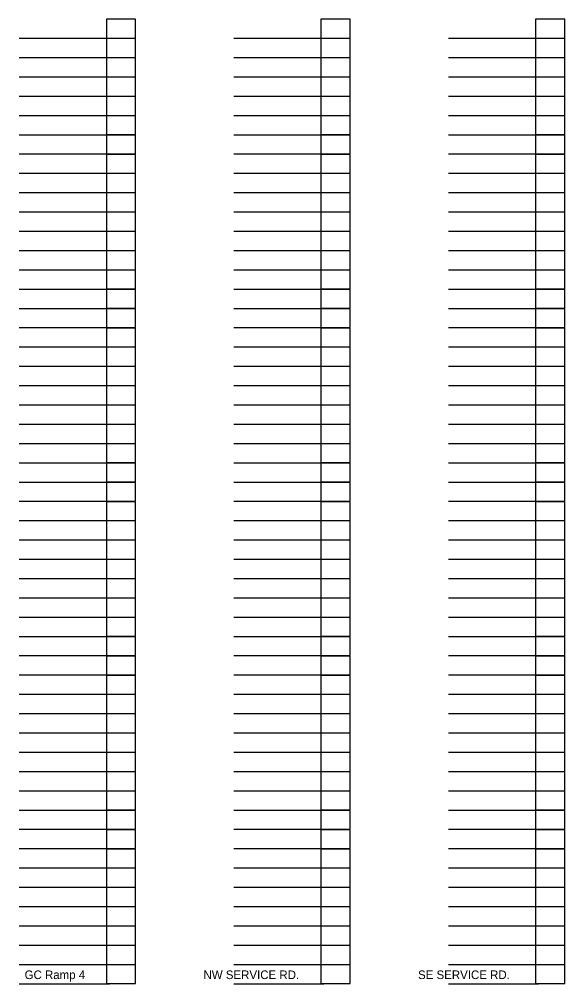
# Model space of a CAD drawing. Extents: x 625451 to 4181825, y 337941 to 441164.
# Drawn here: x 704151 to 716862, y 373673 to 396164 of the extents above; entities that cross this region are included whole.
import ezdxf

# ---------------------------------------------------------------- set-up
doc = ezdxf.new("R2010")
doc.units = 0
for name, color, linetype in [('PLOT_BDR-NOTUSED', 7, 'Continuous'), ('R_CX_Layout-GCRamp4', 7, 'Continuous'), ('R_CX_LAYOUT-NW SERVICE RD', 7, 'Continuous'), ('R_CX_LAYOUT-SE SERVICE RD', 7, 'Continuous'), ('R_No Plot_SEG2_FR', 7, 'Continuous')]:
    doc.layers.add(name, color=color, linetype=linetype)

msp = doc.modelspace()

# ---------------------------------------------------------------- linework, layer by layer
at = {"layer": 'PLOT_BDR-NOTUSED'}
for points in [[(706862, 396164), (706182, 396164), (706182, 395724), (706862, 395724)], [(711862, 396164), (711182, 396164), (711182, 395724), (711862, 395724)], [(716862, 396164), (716182, 396164), (716182, 395724), (716862, 395724)], [(706862, 395714), (706182, 395714), (706182, 395274), (706862, 395274)], [(711862, 395714), (711182, 395714), (711182, 395274), (711862, 395274)], [(716862, 395714), (716182, 395714), (716182, 395274), (716862, 395274)], [(706862, 395264), (706182, 395264), (706182, 394824), (706862, 394824)], [(711862, 395264), (711182, 395264), (711182, 394824), (711862, 394824)], [(716862, 395264), (716182, 395264), (716182, 394824), (716862, 394824)], [(706862, 394814), (706182, 394814), (706182, 394374), (706862, 394374)], [(711862, 394814), (711182, 394814), (711182, 394374), (711862, 394374)], [(716862, 394814), (716182, 394814), (716182, 394374), (716862, 394374)], [(706862, 394364), (706182, 394364), (706182, 393924), (706862, 393924)], [(711862, 394364), (711182, 394364), (711182, 393924), (711862, 393924)], [(716862, 394364), (716182, 394364), (716182, 393924), (716862, 393924)], [(706862, 393914), (706182, 393914), (706182, 393474), (706862, 393474)], [(711862, 393914), (711182, 393914), (711182, 393474), (711862, 393474)], [(716862, 393914), (716182, 393914), (716182, 393474), (716862, 393474)], [(706862, 393464), (706182, 393464), (706182, 393024), (706862, 393024)], [(711862, 393464), (711182, 393464), (711182, 393024), (711862, 393024)], [(716862, 393464), (716182, 393464), (716182, 393024), (716862, 393024)], [(706862, 393014), (706182, 393014), (706182, 392574), (706862, 392574)], [(711862, 393014), (711182, 393014), (711182, 392574), (711862, 392574)], [(716862, 393014), (716182, 393014), (716182, 392574), (716862, 392574)], [(706862, 392564), (706182, 392564), (706182, 392124), (706862, 392124)], [(711862, 392564), (711182, 392564), (711182, 392124), (711862, 392124)], [(716862, 392564), (716182, 392564), (716182, 392124), (716862, 392124)], [(706862, 392114), (706182, 392114), (706182, 391674), (706862, 391674)], [(711862, 392114), (711182, 392114), (711182, 391674), (711862, 391674)], [(716862, 392114), (716182, 392114), (716182, 391674), (716862, 391674)], [(706862, 391664), (706182, 391664), (706182, 391224), (706862, 391224)], [(711862, 391664), (711182, 391664), (711182, 391224), (711862, 391224)], [(716862, 391664), (716182, 391664), (716182, 391224), (716862, 391224)], [(706862, 391214), (706182, 391214), (706182, 390774), (706862, 390774)], [(711862, 391214), (711182, 391214), (711182, 390774), (711862, 390774)], [(716862, 391214), (716182, 391214), (716182, 390774), (716862, 390774)], [(706862, 390764), (706182, 390764), (706182, 390324), (706862, 390324)], [(711862, 390764), (711182, 390764), (711182, 390324), (711862, 390324)], [(716862, 390764), (716182, 390764), (716182, 390324), (716862, 390324)], [(706862, 390314), (706182, 390314), (706182, 389874), (706862, 389874)], [(711862, 390314), (711182, 390314), (711182, 389874), (711862, 389874)], [(716862, 390314), (716182, 390314), (716182, 389874), (716862, 389874)], [(706862, 389864), (706182, 389864), (706182, 389424), (706862, 389424)], [(711862, 389864), (711182, 389864), (711182, 389424), (711862, 389424)], [(716862, 389864), (716182, 389864), (716182, 389424), (716862, 389424)], [(706862, 389414), (706182, 389414), (706182, 388974), (706862, 388974)], [(711862, 389414), (711182, 389414), (711182, 388974), (711862, 388974)], [(716862, 389414), (716182, 389414), (716182, 388974), (716862, 388974)], [(706862, 388964), (706182, 388964), (706182, 388524), (706862, 388524)], [(711862, 388964), (711182, 388964), (711182, 388524), (711862, 388524)], [(716862, 388964), (716182, 388964), (716182, 388524), (716862, 388524)], [(706862, 388514), (706182, 388514), (706182, 388074), (706862, 388074)], [(711862, 388514), (711182, 388514), (711182, 388074), (711862, 388074)], [(716862, 388514), (716182, 388514), (716182, 388074), (716862, 388074)], [(706862, 388064), (706182, 388064), (706182, 387624), (706862, 387624)], [(711862, 388064), (711182, 388064), (711182, 387624), (711862, 387624)], [(716862, 388064), (716182, 388064), (716182, 387624), (716862, 387624)], [(706862, 387614), (706182, 387614), (706182, 387174), (706862, 387174)], [(711862, 387614), (711182, 387614), (711182, 387174), (711862, 387174)], [(716862, 387614), (716182, 387614), (716182, 387174), (716862, 387174)], [(706862, 387164), (706182, 387164), (706182, 386724), (706862, 386724)], [(711862, 387164), (711182, 387164), (711182, 386724), (711862, 386724)], [(716862, 387164), (716182, 387164), (716182, 386724), (716862, 386724)], [(706862, 386714), (706182, 386714), (706182, 386274), (706862, 386274)], [(711862, 386714), (711182, 386714), (711182, 386274), (711862, 386274)], [(716862, 386714), (716182, 386714), (716182, 386274), (716862, 386274)], [(706862, 386264), (706182, 386264), (706182, 385824), (706862, 385824)], [(711862, 386264), (711182, 386264), (711182, 385824), (711862, 385824)], [(716862, 386264), (716182, 386264), (716182, 385824), (716862, 385824)], [(706862, 385814), (706182, 385814), (706182, 385374), (706862, 385374)], [(711862, 385814), (711182, 385814), (711182, 385374), (711862, 385374)], [(716862, 385814), (716182, 385814), (716182, 385374), (716862, 385374)], [(706862, 385364), (706182, 385364), (706182, 384924), (706862, 384924)], [(711862, 385364), (711182, 385364), (711182, 384924), (711862, 384924)], [(716862, 385364), (716182, 385364), (716182, 384924), (716862, 384924)], [(706862, 384914), (706182, 384914), (706182, 384474), (706862, 384474)], [(711862, 384914), (711182, 384914), (711182, 384474), (711862, 384474)], [(716862, 384914), (716182, 384914), (716182, 384474), (716862, 384474)], [(706862, 384464), (706182, 384464), (706182, 384024), (706862, 384024)], [(711862, 384464), (711182, 384464), (711182, 384024), (711862, 384024)], [(716862, 384464), (716182, 384464), (716182, 384024), (716862, 384024)], [(706862, 384014), (706182, 384014), (706182, 383574), (706862, 383574)], [(711862, 384014), (711182, 384014), (711182, 383574), (711862, 383574)], [(716862, 384014), (716182, 384014), (716182, 383574), (716862, 383574)], [(706862, 383564), (706182, 383564), (706182, 383124), (706862, 383124)], [(711862, 383564), (711182, 383564), (711182, 383124), (711862, 383124)], [(716862, 383564), (716182, 383564), (716182, 383124), (716862, 383124)], [(706862, 383114), (706182, 383114), (706182, 382674), (706862, 382674)], [(711862, 383114), (711182, 383114), (711182, 382674), (711862, 382674)], [(716862, 383114), (716182, 383114), (716182, 382674), (716862, 382674)], [(706862, 382664), (706182, 382664), (706182, 382224), (706862, 382224)], [(711862, 382664), (711182, 382664), (711182, 382224), (711862, 382224)], [(716862, 382664), (716182, 382664), (716182, 382224), (716862, 382224)], [(706862, 382214), (706182, 382214), (706182, 381774), (706862, 381774)], [(711862, 382214), (711182, 382214), (711182, 381774), (711862, 381774)], [(716862, 382214), (716182, 382214), (716182, 381774), (716862, 381774)], [(706862, 381764), (706182, 381764), (706182, 381324), (706862, 381324)], [(711862, 381764), (711182, 381764), (711182, 381324), (711862, 381324)], [(716862, 381764), (716182, 381764), (716182, 381324), (716862, 381324)], [(706862, 381314), (706182, 381314), (706182, 380874), (706862, 380874)], [(711862, 381314), (711182, 381314), (711182, 380874), (711862, 380874)], [(716862, 381314), (716182, 381314), (716182, 380874), (716862, 380874)], [(706862, 380864), (706182, 380864), (706182, 380424), (706862, 380424)], [(711862, 380864), (711182, 380864), (711182, 380424), (711862, 380424)], [(716862, 380864), (716182, 380864), (716182, 380424), (716862, 380424)], [(706862, 380414), (706182, 380414), (706182, 379974), (706862, 379974)], [(711862, 380414), (711182, 380414), (711182, 379974), (711862, 379974)], [(716862, 380414), (716182, 380414), (716182, 379974), (716862, 379974)], [(706862, 379964), (706182, 379964), (706182, 379524), (706862, 379524)], [(711862, 379964), (711182, 379964), (711182, 379524), (711862, 379524)], [(716862, 379964), (716182, 379964), (716182, 379524), (716862, 379524)], [(706862, 379514), (706182, 379514), (706182, 379074), (706862, 379074)], [(711862, 379514), (711182, 379514), (711182, 379074), (711862, 379074)], [(716862, 379514), (716182, 379514), (716182, 379074), (716862, 379074)], [(706862, 379064), (706182, 379064), (706182, 378624), (706862, 378624)], [(711862, 379064), (711182, 379064), (711182, 378624), (711862, 378624)], [(716862, 379064), (716182, 379064), (716182, 378624), (716862, 378624)], [(706862, 378614), (706182, 378614), (706182, 378174), (706862, 378174)], [(711862, 378614), (711182, 378614), (711182, 378174), (711862, 378174)], [(716862, 378614), (716182, 378614), (716182, 378174), (716862, 378174)], [(711862, 378164), (711182, 378164), (711182, 377724), (711862, 377724)], [(716862, 378164), (716182, 378164), (716182, 377724), (716862, 377724)], [(711862, 377714), (711182, 377714), (711182, 377274), (711862, 377274)], [(716862, 377714), (716182, 377714), (716182, 377274), (716862, 377274)], [(711862, 377264), (711182, 377264), (711182, 376824), (711862, 376824)], [(716862, 377264), (716182, 377264), (716182, 376824), (716862, 376824)], [(711862, 376814), (711182, 376814), (711182, 376374), (711862, 376374)], [(716862, 376814), (716182, 376814), (716182, 376374), (716862, 376374)], [(711862, 376364), (711182, 376364), (711182, 375924), (711862, 375924)]]:
    msp.add_lwpolyline(points, close=True, dxfattribs=at)
at = {"layer": 'R_CX_Layout-GCRamp4'}
for p, q in [((704151, 395723), (706250, 395723)), ((704151, 395273), (706250, 395273)), ((704151, 394823), (706250, 394823)), ((704151, 394373), (706250, 394373)), ((704151, 393923), (706250, 393923)), ((704151, 393473), (706250, 393473)), ((704151, 393023), (706250, 393023)), ((704151, 392573), (706250, 392573)), ((704151, 392123), (706250, 392123)), ((704151, 391673), (706250, 391673)), ((704151, 391223), (706250, 391223)), ((704151, 390773), (706250, 390773)), ((704151, 390323), (706250, 390323)), ((704151, 389873), (706250, 389873)), ((704151, 389423), (706250, 389423)), ((704151, 388973), (706250, 388973)), ((704151, 388523), (706250, 388523)), ((704151, 388073), (706250, 388073)), ((704151, 387623), (706250, 387623)), ((704151, 387173), (706250, 387173)), ((704151, 386723), (706250, 386723)), ((704151, 386273), (706250, 386273)), ((704151, 385823), (706250, 385823)), ((704151, 385373), (706250, 385373)), ((704151, 384923), (706250, 384923)), ((704151, 384473), (706250, 384473)), ((704151, 384023), (706250, 384023)), ((704151, 383573), (706250, 383573)), ((704151, 383123), (706250, 383123)), ((704151, 382673), (706250, 382673)), ((704151, 382223), (706250, 382223)), ((704151, 381773), (706250, 381773)), ((704151, 381323), (706250, 381323)), ((704151, 380873), (706250, 380873)), ((704151, 380423), (706250, 380423)), ((704151, 379973), (706250, 379973)), ((704151, 379523), (706250, 379523)), ((704151, 379073), (706250, 379073)), ((704151, 378623), (706250, 378623)), ((704151, 378173), (706250, 378173)), ((704151, 377723), (706250, 377723)), ((704151, 377273), (706250, 377273)), ((704151, 376823), (706250, 376823)), ((704151, 376373), (706250, 376373)), ((704151, 375923), (706250, 375923)), ((704151, 375473), (706250, 375473)), ((704151, 375023), (706250, 375023)), ((704151, 374573), (706250, 374573)), ((704151, 374123), (706250, 374123)), ((704151, 373673), (706250, 373673))]:
    msp.add_line(p, q, dxfattribs=at)
at = {"layer": 'R_CX_LAYOUT-NW SERVICE RD'}
for p, q in [((709151, 395723), (711250, 395723)), ((709151, 395273), (711250, 395273)), ((709151, 394823), (711250, 394823)), ((709151, 394373), (711250, 394373)), ((709151, 393923), (711250, 393923)), ((709151, 393473), (711250, 393473)), ((709151, 393023), (711250, 393023)), ((709151, 392573), (711250, 392573)), ((709151, 392123), (711250, 392123)), ((709151, 391673), (711250, 391673)), ((709151, 391223), (711250, 391223)), ((709151, 390773), (711250, 390773)), ((709151, 390323), (711250, 390323)), ((709151, 389873), (711250, 389873)), ((709151, 389423), (711250, 389423)), ((709151, 388973), (711250, 388973)), ((709151, 388523), (711250, 388523)), ((709151, 388073), (711250, 388073)), ((709151, 387623), (711250, 387623)), ((709151, 387173), (711250, 387173)), ((709151, 386723), (711250, 386723)), ((709151, 386273), (711250, 386273)), ((709151, 385823), (711250, 385823)), ((709151, 385373), (711250, 385373)), ((709151, 384923), (711250, 384923)), ((709151, 384473), (711250, 384473)), ((709151, 384023), (711250, 384023)), ((709151, 383573), (711250, 383573)), ((709151, 383123), (711250, 383123)), ((709151, 382673), (711250, 382673)), ((709151, 382223), (711250, 382223)), ((709151, 381773), (711250, 381773)), ((709151, 381323), (711250, 381323)), ((709151, 380873), (711250, 380873)), ((709151, 380423), (711250, 380423)), ((709151, 379973), (711250, 379973)), ((709151, 379523), (711250, 379523)), ((709151, 379073), (711250, 379073)), ((709151, 378623), (711250, 378623)), ((709151, 378173), (711250, 378173)), ((709151, 377723), (711250, 377723)), ((709151, 377273), (711250, 377273)), ((709151, 376823), (711250, 376823)), ((709151, 376373), (711250, 376373)), ((709151, 375923), (711250, 375923)), ((709151, 375473), (711250, 375473)), ((709151, 375023), (711250, 375023)), ((709151, 374573), (711250, 374573)), ((709151, 374123), (711250, 374123)), ((709151, 373673), (711250, 373673))]:
    msp.add_line(p, q, dxfattribs=at)
at = {"layer": 'R_CX_LAYOUT-SE SERVICE RD'}
for p, q in [((714151, 395723), (716250, 395723)), ((714151, 395273), (716250, 395273)), ((714151, 394823), (716250, 394823)), ((714151, 394373), (716250, 394373)), ((714151, 393923), (716250, 393923)), ((714151, 393473), (716250, 393473)), ((714151, 393023), (716250, 393023)), ((714151, 392573), (716250, 392573)), ((714151, 392123), (716250, 392123)), ((714151, 391673), (716250, 391673)), ((714151, 391223), (716250, 391223)), ((714151, 390773), (716250, 390773)), ((714151, 390323), (716250, 390323)), ((714151, 389873), (716250, 389873)), ((714151, 389423), (716250, 389423)), ((714151, 388973), (716250, 388973)), ((714151, 388523), (716250, 388523)), ((714151, 388073), (716250, 388073)), ((714151, 387623), (716250, 387623)), ((714151, 387173), (716250, 387173)), ((714151, 386723), (716250, 386723)), ((714151, 386273), (716250, 386273)), ((714151, 385823), (716250, 385823)), ((714151, 385373), (716250, 385373)), ((714151, 384923), (716250, 384923)), ((714151, 384473), (716250, 384473)), ((714151, 384023), (716250, 384023)), ((714151, 383573), (716250, 383573)), ((714151, 383123), (716250, 383123)), ((714151, 382673), (716250, 382673)), ((714151, 382223), (716250, 382223)), ((714151, 381773), (716250, 381773)), ((714151, 381323), (716250, 381323)), ((714151, 380873), (716250, 380873)), ((714151, 380423), (716250, 380423)), ((714151, 379973), (716250, 379973)), ((714151, 379523), (716250, 379523)), ((714151, 379073), (716250, 379073)), ((714151, 378623), (716250, 378623)), ((714151, 378173), (716250, 378173)), ((714151, 377723), (716250, 377723)), ((714151, 377273), (716250, 377273)), ((714151, 376823), (716250, 376823)), ((714151, 376373), (716250, 376373)), ((714151, 375923), (716250, 375923)), ((714151, 375473), (716250, 375473)), ((714151, 375023), (716250, 375023)), ((714151, 374573), (716250, 374573)), ((714151, 374123), (716250, 374123)), ((714151, 373673), (716250, 373673))]:
    msp.add_line(p, q, dxfattribs=at)
at = {"layer": 'R_No Plot_SEG2_FR'}
for points in [[(706862, 378164), (706182, 378164), (706182, 377724), (706862, 377724)], [(706862, 377714), (706182, 377714), (706182, 377274), (706862, 377274)], [(706862, 377264), (706182, 377264), (706182, 376824), (706862, 376824)], [(706862, 376814), (706182, 376814), (706182, 376374), (706862, 376374)], [(706862, 376364), (706182, 376364), (706182, 375924), (706862, 375924)], [(716862, 376364), (716182, 376364), (716182, 375924), (716862, 375924)], [(706862, 375914), (706182, 375914), (706182, 375474), (706862, 375474)], [(711862, 375914), (711182, 375914), (711182, 375474), (711862, 375474)], [(716862, 375914), (716182, 375914), (716182, 375474), (716862, 375474)], [(706862, 375464), (706182, 375464), (706182, 375024), (706862, 375024)], [(711862, 375464), (711182, 375464), (711182, 375024), (711862, 375024)], [(716862, 375464), (716182, 375464), (716182, 375024), (716862, 375024)], [(706862, 375014), (706182, 375014), (706182, 374574), (706862, 374574)], [(711862, 375014), (711182, 375014), (711182, 374574), (711862, 374574)], [(716862, 375014), (716182, 375014), (716182, 374574), (716862, 374574)], [(706862, 374564), (706182, 374564), (706182, 374124), (706862, 374124)], [(711862, 374564), (711182, 374564), (711182, 374124), (711862, 374124)], [(716862, 374564), (716182, 374564), (716182, 374124), (716862, 374124)], [(706862, 374114), (706182, 374114), (706182, 373674), (706862, 373674)], [(711862, 374114), (711182, 374114), (711182, 373674), (711862, 373674)], [(716862, 374114), (716182, 374114), (716182, 373674), (716862, 373674)]]:
    msp.add_lwpolyline(points, close=True, dxfattribs=at)

# ---------------------------------------------------------------- texts
at = {"layer": 'R_CX_Layout-GCRamp4'}
msp.add_text('GC Ramp 4', height=200, dxfattribs=at).set_placement((704274, 373781))
at = {"layer": 'R_CX_LAYOUT-NW SERVICE RD'}
msp.add_text('NW SERVICE RD.', height=200, dxfattribs=at).set_placement((708444, 373781))
at = {"layer": 'R_CX_LAYOUT-SE SERVICE RD'}
msp.add_text('SE SERVICE RD.', height=200, dxfattribs=at).set_placement((713444, 373781))

doc.saveas('drawing.dxf')
